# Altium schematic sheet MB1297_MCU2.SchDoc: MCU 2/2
size A4; Date: Not used; ApprovedBy: Not used; CheckedBy: Not used; Author: Not used; CompanyName: STMicroelectronics; DrawnBy: Not used; Engineer: Not used; Organization: Not used; Address1: Not used; Address2: Not used; Address3: Not used; Address4: Not used; DocumentNumber: Not used; Revision: Not used; SheetNumber: 4; SheetTotal: 12
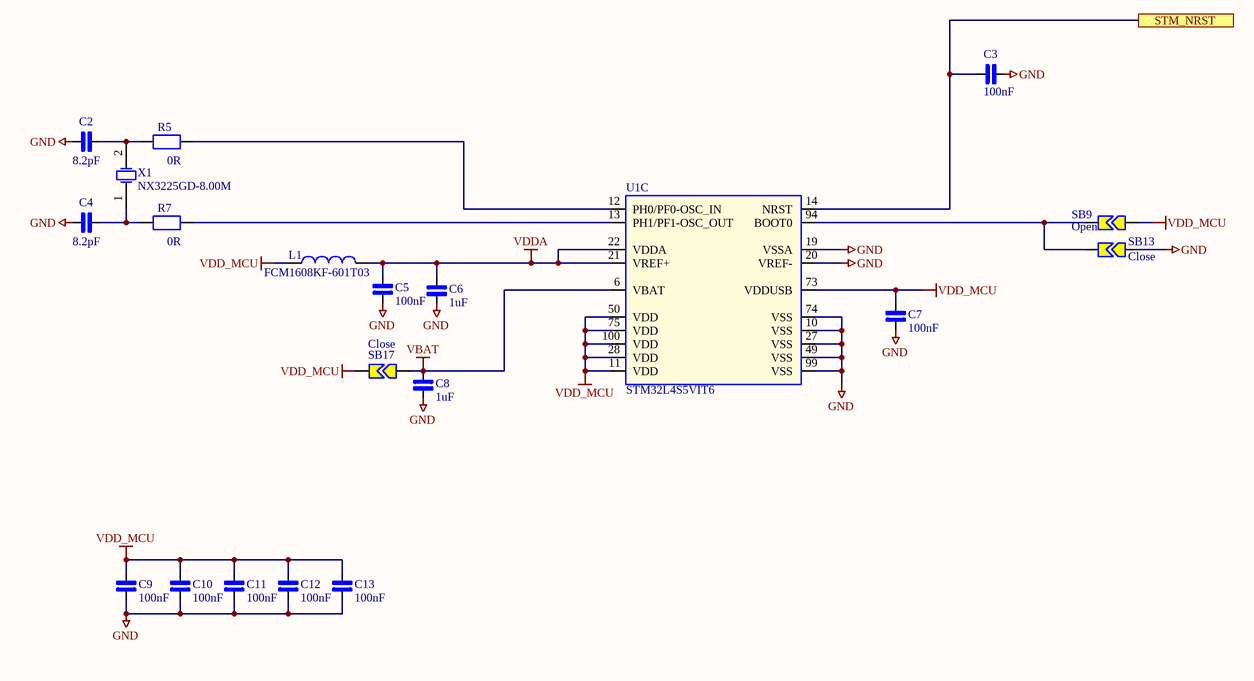
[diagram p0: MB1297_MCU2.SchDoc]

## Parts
C2  8.2pF  [0402]
C3  100nF  [0402]
C4  8.2pF  [0402]
C5  100nF  [0402]
C6  1uF  [0402]
C7  100nF  [0402]
C8  1uF  [0402]
C9  100nF  [0402]
C10  100nF  [0402]
C11  100nF  [0402]
C12  100nF  [0402]
C13  100nF  [0402]
L1  FCM1608KF-601T03  [0603L]
R5  0R  [0402]
R7  0R  [0402]
SB9  Open  [SB]
SB13  Close  [SB]
SB17  Close  [SB]
U1  STM32L4S5VIT6  [LQFP100 14x14x1.6]  (part C of 3)
X1  NX3225GD-8.00M  [CRY_NX3225GD_2P]

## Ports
STM_NRST

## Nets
GND: C2.2 C3.1 C4.2 C5.2 C6.1 C7.2 C8.1 C9.2 C10.2 C11.2 C12.2 C13.2 SB13.1 U1.10(VSS) U1.19(VSSA) U1.20(VREF-) U1.27(VSS) U1.49(VSS) U1.74(VSS) U1.99(VSS)
VBAT: C8.2 SB17.2 U1.6(VBAT)
VDD_MCU: C7.1 C9.1 C10.1 C11.1 C12.1 C13.1 L1.1 SB9.1 SB17.1 U1.11(VDD) U1.28(VDD) U1.50(VDD) U1.73(VDDUSB) U1.75(VDD) U1.100(VDD)
VDDA: C5.1 C6.2 L1.2 U1.21(VREF+) U1.22(VDDA)
STM_NRST: C3.2 U1.14(NRST) ; port STM_NRST
NetC2_1: C2.1 R5.2 X1.2(OSC2)
NetC4_1: C4.1 R7.2 X1.1(OSC1)
NetR5_1: R5.1 U1.12(PH0/PF0-OSC_IN)
NetR7_1: R7.1 U1.13(PH1/PF1-OSC_OUT)
NetSB9_2: SB9.2 SB13.2 U1.94(BOOT0)

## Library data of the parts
C2-C13 = CAP_NPOL: Capacitor_not polarized
L1 = Inductor: Value: 100uH
R5 R7 = RES: Resistor; FITTED: NO
SB9 SB13 SB17 = Strap2: Solder Jumper; Solder: YES
U1 = STM32L475VGTx
X1 = XTAL_8M_NX3225GD: Crystal 8Mhz, 8pF, -+50PPM, SMD; Manuf_1: NDK; Manuf_Part_1: NX3225GD 8MHz EXS00A-CG04874; ECCN_US/EU: EAR99/NEC; NDK Ref: X3127326; Ref St: 9157029; Fitted: NO; Ordered_By: STM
